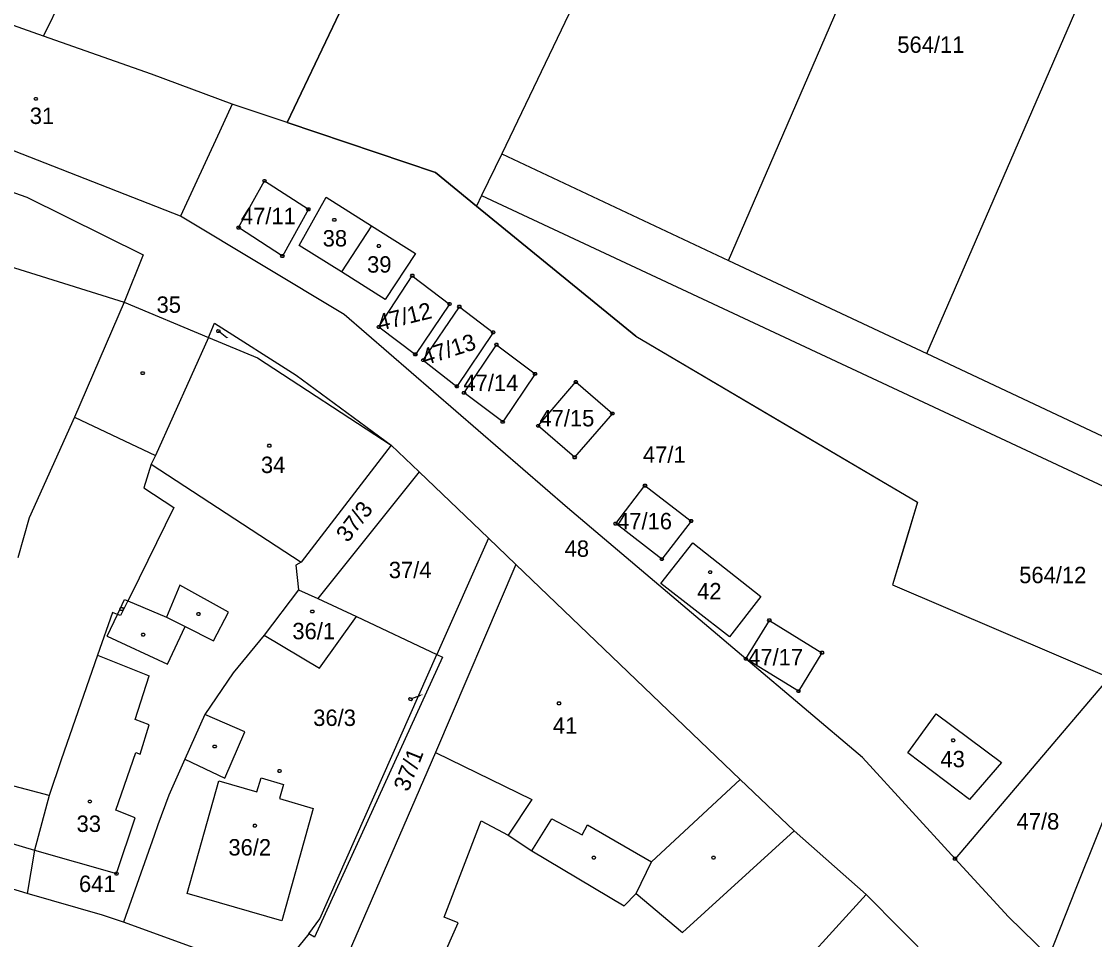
# Model space of a CAD drawing. Extents: x -634640 to -629202, y -1196156 to -1190068.
# Drawn here: x -631473.2 to -631362, y -1192525.3 to -1192430.1 of the extents above; entities that cross this region are included whole.
import ezdxf

# ---------------------------------------------------------------- set-up
doc = ezdxf.new("R2010")
doc.units = 0
for name, color, linetype in [('Obvod převzatý', 7, 'Continuous'), ('Vrstva 1', 7, 'Continuous'), ('Vrstva 2', 7, 'Continuous'), ('Vrstva 3', 7, 'Continuous'), ('Vrstva 4', 7, 'Continuous'), ('Vrstva 5', 7, 'Continuous'), ('Vrstva 7', 7, 'Continuous'), ('Vrstva 8', 7, 'Continuous')]:
    doc.layers.add(name, color=color, linetype=linetype)

msp = doc.modelspace()

# ---------------------------------------------------------------- linework, layer by layer
at = {"layer": 'Obvod převzatý'}
for points in [[(-631430.186, -1192408.103), (-631445.7, -1192440.63)], [(-631445.7, -1192440.63), (-631430.33, -1192445.81), (-631426.07, -1192449.29), (-631417.82, -1192456.025), (-631409.57, -1192462.76), (-631394.975, -1192471.355), (-631380.38, -1192479.95), (-631381.665, -1192484.23), (-631382.95, -1192488.51), (-631371.725, -1192493.305), (-631360.5, -1192498.1), (-631358.72, -1192498.86)]]:
    msp.add_lwpolyline(points, dxfattribs=at)
at = {"layer": 'Vrstva 1'}
for p, q in [((-631445.7, -1192440.63), (-631371.62, -1192285.31)), ((-631470.93, -1192431.68), (-631432.82, -1192354)), ((-631400.85, -1192396.86), (-631423.45, -1192443.85)), ((-631399.95, -1192454.9), (-631379.2, -1192407.07)), ((-631379.4, -1192464.56), (-631358.23, -1192415.75)), ((-631470.93, -1192431.68), (-631480.78, -1192428.21)), ((-631459.75, -1192435.62), (-631470.93, -1192431.68)), ((-631451.37, -1192438.72), (-631459.75, -1192435.62)), ((-631456.75, -1192450.33), (-631490.28, -1192437.19)), ((-631451.37, -1192438.72), (-631452.71, -1192441.6)), ((-631445.7, -1192440.63), (-631451.37, -1192438.72)), ((-631430.33, -1192445.81), (-631445.7, -1192440.63)), ((-631492.01, -1192441.47), (-631472.67, -1192448.35)), ((-631452.71, -1192441.6), (-631456.75, -1192450.33)), ((-631423.45, -1192443.85), (-631425.54, -1192448.18)), ((-631423.45, -1192443.85), (-631399.95, -1192454.9)), ((-631426.07, -1192449.29), (-631430.33, -1192445.81)), ((-631448.03, -1192446.66), (-631443.49, -1192449.6)), ((-631472.67, -1192448.35), (-631460.62, -1192454.34)), ((-631444.43, -1192453.35), (-631441.65, -1192448.34)), ((-631441.65, -1192448.34), (-631436.93, -1192451.32)), ((-631425.54, -1192448.18), (-631426.07, -1192449.29)), ((-631425.54, -1192448.18), (-631337.99, -1192489.11)), ((-631494.64, -1192449.21), (-631462.58, -1192459.22)), ((-631443.49, -1192449.6), (-631446.18, -1192454.45)), ((-631409.57, -1192462.76), (-631426.07, -1192449.29)), ((-631439.77, -1192460.5), (-631456.75, -1192450.33)), ((-631436.93, -1192451.32), (-631440.07, -1192456.09)), ((-631436.93, -1192451.32), (-631432.4, -1192454.19)), ((-631440.07, -1192456.09), (-631444.43, -1192453.35)), ((-631432.4, -1192454.19), (-631435.52, -1192458.94)), ((-631460.62, -1192454.34), (-631462.58, -1192459.22)), ((-631399.95, -1192454.9), (-631379.4, -1192464.56)), ((-631435.52, -1192458.94), (-631440.07, -1192456.09)), ((-631436.19, -1192461.79), (-631432.72, -1192456.49)), ((-631462.58, -1192459.22), (-631467.73, -1192471.14)), ((-631462.58, -1192459.22), (-631453.83, -1192462.89)), ((-631431.6, -1192465.24), (-631427.84, -1192459.7)), ((-631416.65, -1192480.53), (-631439.77, -1192460.5)), ((-631453.83, -1192462.89), (-631453.22, -1192461.42)), ((-631453.22, -1192461.42), (-631444.75, -1192466.8)), ((-631436.19, -1192461.79), (-631432.4, -1192464.64)), ((-631453.83, -1192462.89), (-631459.33, -1192475.11)), ((-631453.83, -1192462.89), (-631448.75, -1192465.01)), ((-631409.57, -1192462.76), (-631380.38, -1192479.95)), ((-631448.75, -1192465.01), (-631434.91, -1192474.04)), ((-631431.6, -1192465.24), (-631428.11, -1192467.95)), ((-631379.4, -1192464.56), (-631358.97, -1192474.17)), ((-631444.75, -1192466.8), (-631434.91, -1192474.04)), ((-631467.73, -1192471.14), (-631472.4, -1192481.56)), ((-631434.91, -1192474.04), (-631444.23, -1192486.15)), ((-631434.91, -1192474.04), (-631432, -1192476.82)), ((-631459.33, -1192475.11), (-631459.77, -1192476.01)), ((-631459.77, -1192476.01), (-631460.52, -1192478.47)), ((-631459.77, -1192476.01), (-631444.23, -1192486.15)), ((-631432, -1192476.82), (-631442.52, -1192489.94)), ((-631432, -1192476.82), (-631424.83, -1192483.68)), ((-631460.52, -1192478.47), (-631457.44, -1192480.51)), ((-631457.44, -1192480.51), (-631461.93, -1192489.64)), ((-631398.16, -1192496.18), (-631416.65, -1192480.53)), ((-631380.38, -1192479.95), (-631382.95, -1192488.51)), ((-631472.4, -1192481.56), (-631473.59, -1192485.73)), ((-631424.83, -1192483.68), (-631430.17, -1192495.74)), ((-631424.83, -1192483.68), (-631421.99, -1192486.4)), ((-631406.95, -1192488.36), (-631403.65, -1192484.16)), ((-631403.65, -1192484.16), (-631396.59, -1192489.71)), ((-631444.23, -1192486.15), (-631444.79, -1192486.46)), ((-631444.79, -1192486.46), (-631444.51, -1192489.03)), ((-631421.99, -1192486.4), (-631430.31, -1192505.87)), ((-631421.99, -1192486.4), (-631398.74, -1192508.67)), ((-631399.85, -1192493.91), (-631406.95, -1192488.36)), ((-631382.95, -1192488.51), (-631360.5, -1192498.1)), ((-631461.93, -1192489.64), (-631462.2, -1192490.18)), ((-631444.51, -1192489.03), (-631448.06, -1192493.71)), ((-631444.51, -1192489.03), (-631442.52, -1192489.94)), ((-631396.59, -1192489.71), (-631399.85, -1192493.91)), ((-631462.2, -1192490.18), (-631462.94, -1192491.69)), ((-631442.52, -1192489.94), (-631438.5, -1192491.79)), ((-631463.79, -1192491.37), (-631465.32, -1192495.78)), ((-631463.27, -1192491.57), (-631463.79, -1192491.37)), ((-631462.94, -1192491.69), (-631463.27, -1192491.57)), ((-631438.5, -1192491.79), (-631430.17, -1192495.74)), ((-631448.06, -1192493.71), (-631451.27, -1192497.61)), ((-631465.32, -1192495.78), (-631469.09, -1192506.65)), ((-631429.59, -1192496.02), (-631442.85, -1192525.01)), ((-631442.29, -1192523.1), (-631430.17, -1192495.74)), ((-631430.17, -1192495.74), (-631429.59, -1192496.02)), ((-631386.08, -1192506.4), (-631398.16, -1192496.18)), ((-631451.27, -1192497.61), (-631454.2, -1192501.95)), ((-631360.5, -1192498.1), (-631376.48, -1192516.88)), ((-631454.2, -1192501.95), (-631456.29, -1192506.58)), ((-631381.38, -1192505.91), (-631378.45, -1192501.86)), ((-631378.45, -1192501.86), (-631371.67, -1192506.93)), ((-631363.92, -1192519.95), (-631357.94, -1192504.95)), ((-631430.31, -1192505.87), (-631440.64, -1192529.68)), ((-631430.31, -1192505.87), (-631420.33, -1192510.75)), ((-631376.48, -1192516.88), (-631386.08, -1192506.4)), ((-631374.98, -1192510.76), (-631381.38, -1192505.91)), ((-631469.09, -1192506.65), (-631470.36, -1192510.33)), ((-631456.29, -1192506.58), (-631457.94, -1192510.3)), ((-631371.67, -1192506.93), (-631374.98, -1192510.76)), ((-631448.81, -1192509.97), (-631448.37, -1192508.5)), ((-631448.37, -1192508.5), (-631446.06, -1192509.2)), ((-631407.93, -1192517.22), (-631398.74, -1192508.67)), ((-631398.74, -1192508.67), (-631393.14, -1192513.98)), ((-631456.04, -1192520.49), (-631452.76, -1192508.82)), ((-631452.76, -1192508.82), (-631448.81, -1192509.97)), ((-631446.06, -1192509.2), (-631446.49, -1192510.65)), ((-631470.36, -1192510.33), (-631471.87, -1192516.01)), ((-631457.94, -1192510.3), (-631459.07, -1192513.38)), ((-631446.49, -1192510.65), (-631442.98, -1192511.68)), ((-631420.33, -1192510.75), (-631422.77, -1192514.44)), ((-631442.98, -1192511.68), (-631446.24, -1192523.32)), ((-631420.33, -1192516.05), (-631418.27, -1192512.74)), ((-631418.27, -1192512.74), (-631415.1, -1192514.41)), ((-631459.07, -1192513.38), (-631459.48, -1192514.48)), ((-631415.1, -1192514.41), (-631414.55, -1192513.37)), ((-631414.55, -1192513.37), (-631407.93, -1192517.22)), ((-631393.14, -1192513.98), (-631385.7, -1192520.6)), ((-631474.77, -1192515.13), (-631471.87, -1192516.01)), ((-631459.48, -1192514.48), (-631462.64, -1192523.46)), ((-631422.77, -1192514.44), (-631420.33, -1192516.05)), ((-631471.87, -1192516.01), (-631472.64, -1192520.48)), ((-631370.95, -1192522.92), (-631376.48, -1192516.88)), ((-631472.64, -1192520.48), (-631476.38, -1192519.35)), ((-631464.81, -1192522.73), (-631472.64, -1192520.48)), ((-631446.24, -1192523.32), (-631456.04, -1192520.49)), ((-631385.7, -1192520.6), (-631391.98, -1192527.48)), ((-631385.7, -1192520.6), (-631372.23, -1192534.1)), ((-631366.72, -1192527.02), (-631363.92, -1192519.95)), ((-631462.64, -1192523.46), (-631464.81, -1192522.73)), ((-631443.43, -1192524.68), (-631442.29, -1192523.1)), ((-631366.72, -1192527.02), (-631370.95, -1192522.92)), ((-631447.06, -1192529.09), (-631462.64, -1192523.46)), ((-631443.43, -1192524.68), (-631447.06, -1192529.09)), ((-631442.85, -1192525.01), (-631443.43, -1192524.68))]:
    msp.add_line(p, q, dxfattribs=at)
for points in [[(-631446.18, -1192454.45), (-631450.71, -1192451.51), (-631448.03, -1192446.66)], [(-631432.72, -1192456.49), (-631428.86, -1192459.42), (-631432.4, -1192464.64)], [(-631427.84, -1192459.7), (-631424.34, -1192462.36), (-631428.11, -1192467.95)], [(-631424, -1192463.64), (-631420, -1192466.65), (-631423.35, -1192471.62), (-631427.36, -1192468.62), (-631424, -1192463.64)], [(-631415.77, -1192467.49), (-631411.99, -1192470.76), (-631415.9, -1192475.3), (-631419.68, -1192472.04), (-631415.77, -1192467.49)], [(-631411.64, -1192482.17), (-631408.61, -1192478.23), (-631403.83, -1192481.9), (-631406.86, -1192485.85), (-631411.64, -1192482.17)], [(-631398.16, -1192496.18), (-631395.72, -1192492.19), (-631390.27, -1192495.54), (-631392.71, -1192499.53), (-631398.16, -1192496.18)]]:
    msp.add_lwpolyline(points, dxfattribs=at)
at = {"layer": 'Vrstva 3'}
for points in [[(-631471.64, -1192438.01), (-631471.55, -1192438.16), (-631471.64, -1192438.31), (-631471.82, -1192438.31), (-631471.91, -1192438.16), (-631471.82, -1192438.01), (-631471.64, -1192438.01)], [(-631447.44, -1192473.95), (-631447.35, -1192474.1), (-631447.44, -1192474.25), (-631447.62, -1192474.25), (-631447.71, -1192474.1), (-631447.62, -1192473.95), (-631447.44, -1192473.95)], [(-631417.43, -1192500.64), (-631417.34, -1192500.79), (-631417.43, -1192500.94), (-631417.61, -1192500.94), (-631417.7, -1192500.79), (-631417.61, -1192500.64), (-631417.43, -1192500.64)]]:
    msp.add_lwpolyline(points, dxfattribs=at)
at = {"layer": 'Vrstva 4'}
for p, q in [((-631467.73, -1192471.14), (-631459.33, -1192475.11)), ((-631456.81, -1192488.54), (-631458.18, -1192491.86)), ((-631451.78, -1192491.34), (-631456.81, -1192488.54)), ((-631462.2, -1192490.18), (-631458.18, -1192491.86)), ((-631464.33, -1192493.83), (-631463.27, -1192491.57)), ((-631458.18, -1192491.86), (-631456.26, -1192492.83)), ((-631453.33, -1192494.31), (-631451.78, -1192491.34)), ((-631442.32, -1192497.13), (-631438.5, -1192491.79)), ((-631456.26, -1192492.83), (-631453.33, -1192494.31)), ((-631448.06, -1192493.71), (-631442.32, -1192497.13)), ((-631465.32, -1192495.78), (-631459.98, -1192497.95)), ((-631461.45, -1192502.47), (-631459.98, -1192497.95)), ((-631450.07, -1192503.75), (-631454.2, -1192501.95)), ((-631459.97, -1192503.01), (-631461.45, -1192502.47)), ((-631452.14, -1192508.54), (-631450.07, -1192503.75)), ((-631456.29, -1192506.58), (-631452.14, -1192508.54)), ((-631470.36, -1192510.33), (-631476.29, -1192508.78)), ((-631463.37, -1192518.42), (-631461.44, -1192512.65)), ((-631429.42, -1192522.93), (-631425.57, -1192512.95)), ((-631425.57, -1192512.95), (-631422.77, -1192514.44)), ((-631404.73, -1192524.53), (-631393.14, -1192513.98)), ((-631471.87, -1192516.01), (-631463.37, -1192518.42)), ((-631420.33, -1192516.05), (-631410.77, -1192521.77)), ((-631409.52, -1192520.47), (-631407.93, -1192517.22)), ((-631410.77, -1192521.77), (-631409.52, -1192520.47)), ((-631409.52, -1192520.47), (-631404.73, -1192524.53)), ((-631427.95, -1192523.53), (-631429.42, -1192522.93)), ((-631429.73, -1192527.48), (-631427.95, -1192523.53))]:
    msp.add_line(p, q, dxfattribs=at)
for points in [[(-631463.27, -1192491.57), (-631462.55, -1192490.03), (-631462.2, -1192490.18)], [(-631464.33, -1192493.83), (-631458.08, -1192496.73), (-631456.26, -1192492.83)], [(-631461.44, -1192512.65), (-631463.45, -1192511.86), (-631461.35, -1192505.89), (-631460.9, -1192506.06), (-631459.97, -1192503.01)]]:
    msp.add_lwpolyline(points, dxfattribs=at)
at = {"layer": 'Vrstva 5'}
for points in [[(-631440.7, -1192450.55), (-631440.61, -1192450.7), (-631440.7, -1192450.85), (-631440.88, -1192450.85), (-631440.97, -1192450.7), (-631440.88, -1192450.55), (-631440.7, -1192450.55)], [(-631436.09, -1192453.25), (-631436, -1192453.4), (-631436.09, -1192453.55), (-631436.27, -1192453.55), (-631436.36, -1192453.4), (-631436.27, -1192453.25), (-631436.09, -1192453.25)], [(-631460.56, -1192466.43), (-631460.47, -1192466.58), (-631460.56, -1192466.73), (-631460.74, -1192466.73), (-631460.83, -1192466.58), (-631460.74, -1192466.43), (-631460.56, -1192466.43)], [(-631401.77, -1192487.05), (-631401.68, -1192487.2), (-631401.77, -1192487.35), (-631401.95, -1192487.35), (-631402.04, -1192487.2), (-631401.95, -1192487.05), (-631401.77, -1192487.05)], [(-631462.74, -1192490.87), (-631462.65, -1192491.02), (-631462.74, -1192491.17), (-631462.92, -1192491.17), (-631463.01, -1192491.02), (-631462.92, -1192490.87), (-631462.74, -1192490.87)], [(-631454.79, -1192491.39), (-631454.7, -1192491.54), (-631454.79, -1192491.69), (-631454.97, -1192491.69), (-631455.06, -1192491.54), (-631454.97, -1192491.39), (-631454.79, -1192491.39)], [(-631442.98, -1192491.12), (-631442.89, -1192491.27), (-631442.98, -1192491.42), (-631443.16, -1192491.42), (-631443.25, -1192491.27), (-631443.16, -1192491.12), (-631442.98, -1192491.12)], [(-631460.51, -1192493.52), (-631460.42, -1192493.67), (-631460.51, -1192493.82), (-631460.69, -1192493.82), (-631460.78, -1192493.67), (-631460.69, -1192493.52), (-631460.51, -1192493.52)], [(-631453.1, -1192505.11), (-631453.01, -1192505.26), (-631453.1, -1192505.41), (-631453.28, -1192505.41), (-631453.37, -1192505.26), (-631453.28, -1192505.11), (-631453.1, -1192505.11)], [(-631376.58, -1192504.46), (-631376.49, -1192504.61), (-631376.58, -1192504.76), (-631376.76, -1192504.76), (-631376.85, -1192504.61), (-631376.76, -1192504.46), (-631376.58, -1192504.46)], [(-631446.38, -1192507.64), (-631446.29, -1192507.79), (-631446.38, -1192507.94), (-631446.56, -1192507.94), (-631446.65, -1192507.79), (-631446.56, -1192507.64), (-631446.38, -1192507.64)], [(-631466.04, -1192510.81), (-631465.95, -1192510.96), (-631466.04, -1192511.11), (-631466.22, -1192511.11), (-631466.31, -1192510.96), (-631466.22, -1192510.81), (-631466.04, -1192510.81)], [(-631448.94, -1192513.31), (-631448.85, -1192513.46), (-631448.94, -1192513.61), (-631449.12, -1192513.61), (-631449.21, -1192513.46), (-631449.12, -1192513.31), (-631448.94, -1192513.31)], [(-631413.82, -1192516.63), (-631413.73, -1192516.78), (-631413.82, -1192516.93), (-631414, -1192516.93), (-631414.09, -1192516.78), (-631414, -1192516.63), (-631413.82, -1192516.63)], [(-631401.42, -1192516.63), (-631401.33, -1192516.78), (-631401.42, -1192516.93), (-631401.6, -1192516.93), (-631401.69, -1192516.78), (-631401.6, -1192516.63), (-631401.42, -1192516.63)]]:
    msp.add_lwpolyline(points, dxfattribs=at)
at = {"layer": 'Vrstva 7'}
for p, q in [((-631451.94, -1192462.93), (-631452.81, -1192462.22)), ((-631431.88, -1192499.96), (-631432.91, -1192500.36))]:
    msp.add_line(p, q, dxfattribs=at)
for points in [[(-631452.87, -1192462.056), (-631452.696, -1192462.08), (-631452.637, -1192462.245), (-631452.75, -1192462.384), (-631452.924, -1192462.36), (-631452.983, -1192462.195), (-631452.87, -1192462.056)], [(-631433.082, -1192500.33), (-631432.974, -1192500.192), (-631432.802, -1192500.222), (-631432.738, -1192500.39), (-631432.846, -1192500.528), (-631433.018, -1192500.498), (-631433.082, -1192500.33)]]:
    msp.add_lwpolyline(points, dxfattribs=at)
at = {"layer": 'Vrstva 8'}
for points in [[(-631447.94, -1192446.51), (-631447.85, -1192446.66), (-631447.94, -1192446.81), (-631448.12, -1192446.81), (-631448.21, -1192446.66), (-631448.12, -1192446.51), (-631447.94, -1192446.51)], [(-631443.4, -1192449.45), (-631443.31, -1192449.6), (-631443.4, -1192449.75), (-631443.58, -1192449.75), (-631443.67, -1192449.6), (-631443.58, -1192449.45), (-631443.4, -1192449.45)], [(-631450.62, -1192451.36), (-631450.53, -1192451.51), (-631450.62, -1192451.66), (-631450.8, -1192451.66), (-631450.89, -1192451.51), (-631450.8, -1192451.36), (-631450.62, -1192451.36)], [(-631446.09, -1192454.3), (-631446, -1192454.45), (-631446.09, -1192454.6), (-631446.27, -1192454.6), (-631446.36, -1192454.45), (-631446.27, -1192454.3), (-631446.09, -1192454.3)], [(-631432.63, -1192456.34), (-631432.54, -1192456.49), (-631432.63, -1192456.64), (-631432.81, -1192456.64), (-631432.9, -1192456.49), (-631432.81, -1192456.34), (-631432.63, -1192456.34)], [(-631428.77, -1192459.27), (-631428.68, -1192459.42), (-631428.77, -1192459.57), (-631428.95, -1192459.57), (-631429.04, -1192459.42), (-631428.95, -1192459.27), (-631428.77, -1192459.27)], [(-631427.75, -1192459.55), (-631427.66, -1192459.7), (-631427.75, -1192459.85), (-631427.93, -1192459.85), (-631428.02, -1192459.7), (-631427.93, -1192459.55), (-631427.75, -1192459.55)], [(-631436.1, -1192461.64), (-631436.01, -1192461.79), (-631436.1, -1192461.94), (-631436.28, -1192461.94), (-631436.37, -1192461.79), (-631436.28, -1192461.64), (-631436.1, -1192461.64)], [(-631424.25, -1192462.21), (-631424.16, -1192462.36), (-631424.25, -1192462.51), (-631424.43, -1192462.51), (-631424.52, -1192462.36), (-631424.43, -1192462.21), (-631424.25, -1192462.21)], [(-631423.91, -1192463.49), (-631423.82, -1192463.64), (-631423.91, -1192463.79), (-631424.09, -1192463.79), (-631424.18, -1192463.64), (-631424.09, -1192463.49), (-631423.91, -1192463.49)], [(-631432.31, -1192464.49), (-631432.22, -1192464.64), (-631432.31, -1192464.79), (-631432.49, -1192464.79), (-631432.58, -1192464.64), (-631432.49, -1192464.49), (-631432.31, -1192464.49)], [(-631431.51, -1192465.09), (-631431.42, -1192465.24), (-631431.51, -1192465.39), (-631431.69, -1192465.39), (-631431.78, -1192465.24), (-631431.69, -1192465.09), (-631431.51, -1192465.09)], [(-631419.91, -1192466.5), (-631419.82, -1192466.65), (-631419.91, -1192466.8), (-631420.09, -1192466.8), (-631420.18, -1192466.65), (-631420.09, -1192466.5), (-631419.91, -1192466.5)], [(-631415.68, -1192467.34), (-631415.59, -1192467.49), (-631415.68, -1192467.64), (-631415.86, -1192467.64), (-631415.95, -1192467.49), (-631415.86, -1192467.34), (-631415.68, -1192467.34)], [(-631428.02, -1192467.8), (-631427.93, -1192467.95), (-631428.02, -1192468.1), (-631428.2, -1192468.1), (-631428.29, -1192467.95), (-631428.2, -1192467.8), (-631428.02, -1192467.8)], [(-631427.27, -1192468.47), (-631427.18, -1192468.62), (-631427.27, -1192468.77), (-631427.45, -1192468.77), (-631427.54, -1192468.62), (-631427.45, -1192468.47), (-631427.27, -1192468.47)], [(-631411.9, -1192470.61), (-631411.81, -1192470.76), (-631411.9, -1192470.91), (-631412.08, -1192470.91), (-631412.17, -1192470.76), (-631412.08, -1192470.61), (-631411.9, -1192470.61)], [(-631423.26, -1192471.47), (-631423.17, -1192471.62), (-631423.26, -1192471.77), (-631423.44, -1192471.77), (-631423.53, -1192471.62), (-631423.44, -1192471.47), (-631423.26, -1192471.47)], [(-631419.59, -1192471.89), (-631419.5, -1192472.04), (-631419.59, -1192472.19), (-631419.77, -1192472.19), (-631419.86, -1192472.04), (-631419.77, -1192471.89), (-631419.59, -1192471.89)], [(-631415.81, -1192475.15), (-631415.72, -1192475.3), (-631415.81, -1192475.45), (-631415.99, -1192475.45), (-631416.08, -1192475.3), (-631415.99, -1192475.15), (-631415.81, -1192475.15)], [(-631408.52, -1192478.08), (-631408.43, -1192478.23), (-631408.52, -1192478.38), (-631408.7, -1192478.38), (-631408.79, -1192478.23), (-631408.7, -1192478.08), (-631408.52, -1192478.08)], [(-631411.55, -1192482.02), (-631411.46, -1192482.17), (-631411.55, -1192482.32), (-631411.73, -1192482.32), (-631411.82, -1192482.17), (-631411.73, -1192482.02), (-631411.55, -1192482.02)], [(-631403.74, -1192481.75), (-631403.65, -1192481.9), (-631403.74, -1192482.05), (-631403.92, -1192482.05), (-631404.01, -1192481.9), (-631403.92, -1192481.75), (-631403.74, -1192481.75)], [(-631406.77, -1192485.7), (-631406.68, -1192485.85), (-631406.77, -1192486), (-631406.95, -1192486), (-631407.04, -1192485.85), (-631406.95, -1192485.7), (-631406.77, -1192485.7)], [(-631395.63, -1192492.04), (-631395.54, -1192492.19), (-631395.63, -1192492.34), (-631395.81, -1192492.34), (-631395.9, -1192492.19), (-631395.81, -1192492.04), (-631395.63, -1192492.04)], [(-631398.07, -1192496.03), (-631397.98, -1192496.18), (-631398.07, -1192496.33), (-631398.25, -1192496.33), (-631398.34, -1192496.18), (-631398.25, -1192496.03), (-631398.07, -1192496.03)], [(-631390.18, -1192495.39), (-631390.09, -1192495.54), (-631390.18, -1192495.69), (-631390.36, -1192495.69), (-631390.45, -1192495.54), (-631390.36, -1192495.39), (-631390.18, -1192495.39)], [(-631392.62, -1192499.38), (-631392.53, -1192499.53), (-631392.62, -1192499.68), (-631392.8, -1192499.68), (-631392.89, -1192499.53), (-631392.8, -1192499.38), (-631392.62, -1192499.38)], [(-631376.39, -1192516.73), (-631376.3, -1192516.88), (-631376.39, -1192517.03), (-631376.57, -1192517.03), (-631376.66, -1192516.88), (-631376.57, -1192516.73), (-631376.39, -1192516.73)], [(-631463.28, -1192518.27), (-631463.19, -1192518.42), (-631463.28, -1192518.57), (-631463.46, -1192518.57), (-631463.55, -1192518.42), (-631463.46, -1192518.27), (-631463.28, -1192518.27)]]:
    msp.add_lwpolyline(points, dxfattribs=at)

# ---------------------------------------------------------------- texts
at = {"layer": 'Vrstva 2'}
for s, height, p in [('564/11', 1.7, (-631382.463, -1192433.4)), ('31', 1.7, (-631472.353, -1192440.77)), ('47/11', 1.7, (-631450.479, -1192451.15)), ('38', 1.7, (-631442.003, -1192453.46)), ('39', 1.7, (-631437.403, -1192456.17)), ('35', 0.1, (-631451.926, -1192462.93)), ('47/14', 1.7, (-631427.417, -1192468.43)), ('47/15', 1.7, (-631419.547, -1192472.1)), ('47/1', 1.7, (-631408.823, -1192475.87)), ('34', 1.7, (-631448.403, -1192476.93)), ('47/16', 1.7, (-631411.497, -1192482.76)), ('48', 1.7, (-631416.933, -1192485.61)), ('37/4', 1.7, (-631435.153, -1192487.82)), ('564/12', 1.7, (-631369.833, -1192488.34)), ('42', 1.7, (-631403.203, -1192490.02)), ('36/1', 1.7, (-631445.143, -1192494.15)), ('47/17', 1.7, (-631397.914, -1192496.85)), ('36/3', 0.1, (-631431.866, -1192499.96)), ('41', 1.7, (-631418.153, -1192503.94)), ('43', 1.7, (-631377.993, -1192507.41)), ('33', 1.7, (-631467.503, -1192514.11)), ('47/8', 1.7, (-631370.105, -1192513.86)), ('36/2', 1.7, (-631451.773, -1192516.55))]:
    msp.add_text(s, height=height, dxfattribs=at).set_placement(p)
for s, rotation, p in [('47/12', 13.69369, (-631436.095, -1192462.209)), ('47/13', 17.6471, (-631431.408, -1192465.787)), ('37/3', 52.48293, (-631439.405, -1192484.212)), ('37/1', 68.41116, (-631433.143, -1192510.019))]:
    msp.add_text(s, height=1.7, rotation=rotation, dxfattribs=at).set_placement(p)
at = {"layer": 'Vrstva 7'}
for s, p in [('35', (-631459.216, -1192460.33)), ('36/3', (-631442.985, -1192503.13))]:
    msp.add_text(s, height=1.7, dxfattribs=at).set_placement(p)
at = {"layer": 'Vrstva 8'}
msp.add_text('641', height=1.7, dxfattribs=at).set_placement((-631467.253, -1192520.33))

doc.saveas('drawing.dxf')
